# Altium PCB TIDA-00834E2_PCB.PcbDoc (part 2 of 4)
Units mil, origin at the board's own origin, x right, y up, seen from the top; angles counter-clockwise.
Board outline 7480.31 x 4133.86 mil, 4 copper layers (Top Layer, GND, PWR, Bottom Layer), stack 61.912 mil thick; 550 components, 248 nets, 1167 pads, 312 vias.
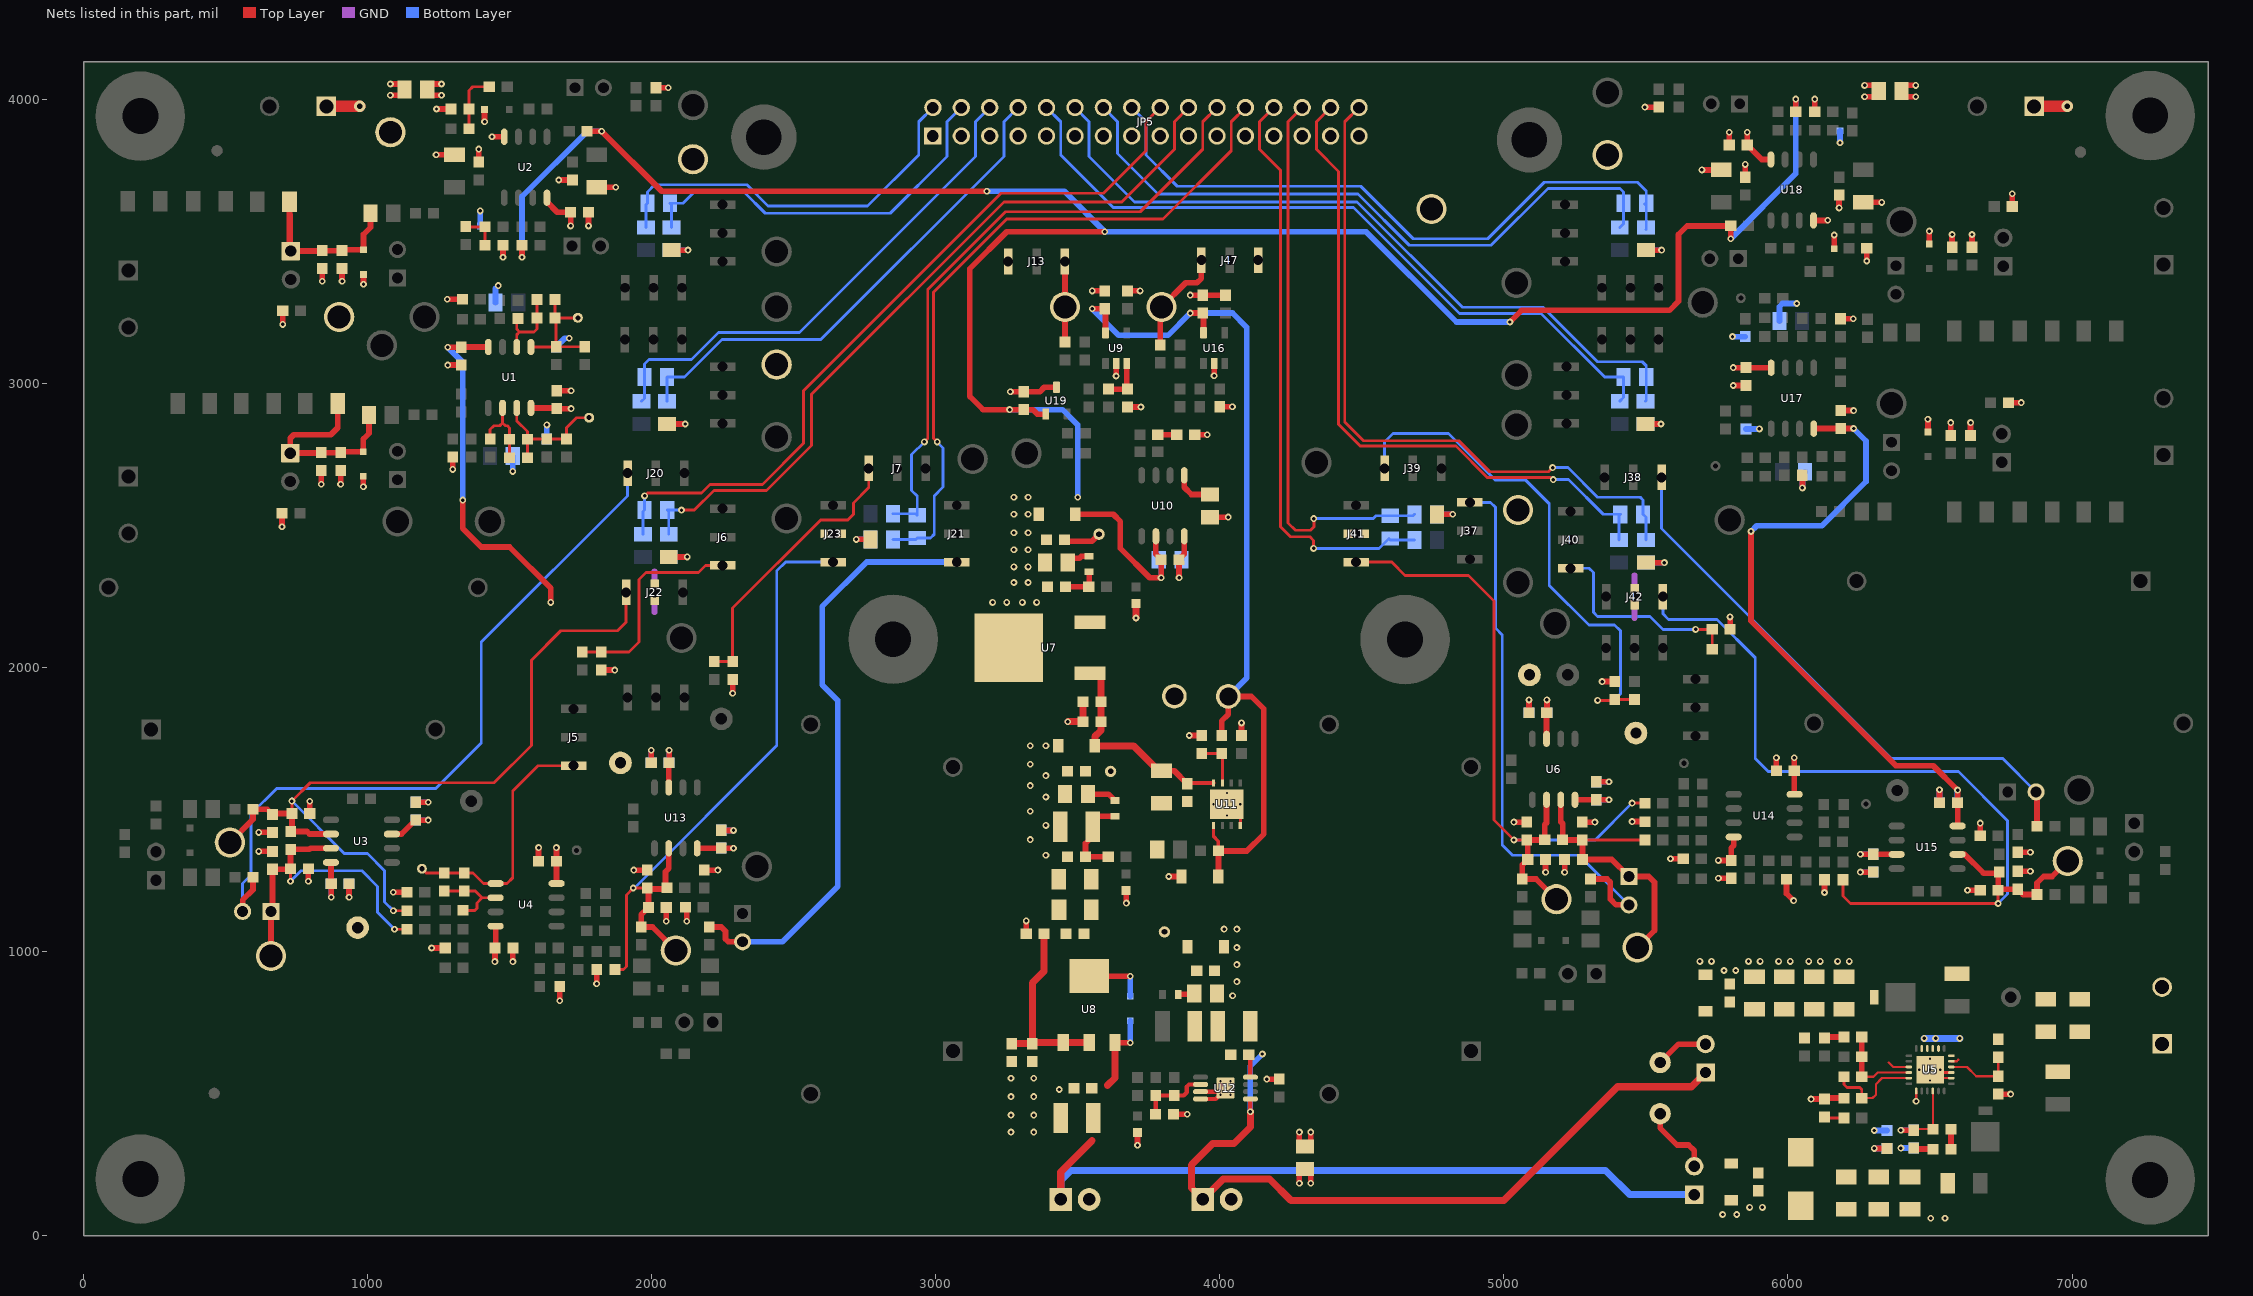
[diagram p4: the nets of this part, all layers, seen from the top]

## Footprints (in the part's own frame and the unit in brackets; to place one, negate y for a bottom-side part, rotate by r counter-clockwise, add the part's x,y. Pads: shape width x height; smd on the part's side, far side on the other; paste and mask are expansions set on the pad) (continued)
TSW-102-07-G-S [mm] "Samtec 100mil, 1x2, 230 mil above insulator"
  rrect6% 1.65x1.65 hole 1.016: 1(-1.27,0)
  round 1.65 hole 1.016: 2(1.27,0)
  silkscreen extent -2.54,-1.27 2.54,1.65, body extent -2.54,-1.27 2.54,1.27, height 8.38
XFMR_CR8350-2500-N [mil] "CURRENT TRANSFORMERS, VERTICAL, 4 PIN, THRU"
  rect 69.06x69.06 / inner round 69.06 / far side rect 69.06x69.06 hole 49.37: 1(-250,500)
  round 69.06 hole 49.37: 2(-250,-500) 3(250,650) 4(250,-650)
  silkscreen extent -317,-738 276,738, body extent -276,-738 276,738, height 1535

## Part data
C1 C2 C4 C5 C19 C20 C82 C84 C88 C90 C99 C100 C101 C102 C104 C105: "CAP, CERM, 100pF, 25V, +/-10%, X7R, 0603"
C3 C6 C9 C66 C103 C106 C110: "CAP, CERM, 0.1uF, 25V, +/-5%, X7R, 0603"
C7 C8 C107 C108: "CAP, CERM, 1000pF, 50V, +/-5%, C0G/NP0, 0603"
C10 C11 C109 C111 C120 C121: "CAP, CERM, 0.01uF, 25V, +/-5%, C0G/NP0, 0603"
C12 C18 C43 C75 C81 C85 C92 C98: library part C1608X5R1C105K, "CAP, CERM, 1 µF, 16 V, +/- 10%, X5R, 0603"
C13 C17 C44 C76 C80 C83 C86 C87 C89 C91 C93 C97: "CAP, CERM, 0.1 µF, 25 V, +/- 10%, X8R, AEC-Q200 Grade 0, 0603"
C14 C16 C47 C52 C77 C79 C94 C96: "CAP, CERM, 1000 pF, 50 V, +/- 10%, X7R, 0603"
C15 C48 C54 C70 C74 C78 C95: library part 06031C103JAT2A, "10000pF 100V Ceramic Capacitor X7R 0603"
C21 C22 C23 C24 C112 C113 C114 C115: "CAP, CERM, 0.01 µF, 50 V, +/- 10%, X7R, 0805"
C25: "CAP, TA, 4.7 µF, 25 V, +/- 10%, 2 ohm, SMD"
C26 C27 C28 C29 C36 C38 C39 C40 C41: "CAP, CERM, 4.7 µF, 25 V, +/- 20%, X7R, 1206"
C30 C33 C35 C42: "CAP, CERM, 0.01 µF, 6.3 V, +/- 10%, X7R, 0603"
C31: library part C0603C224K4RACTU, "CAP, CERM, 0.22 µF, 6.3 V, +/- 10%, X7R, 0603"
C32 C34: "CAP, CERM, 10 pF, 50 V, +/- 5%, C0G/NP0, 0603"
C37: "CAP, CERM, 1 µF, 25 V, +/- 10%, X5R, 0603"
C45 C55 C68: library part C2012X5R1H475K125AB, "CAP, CERM, 4.7uF, 50V, +/-10%, X5R, 0805"
C46 C51 C56 C58 C69 C71 C118 C119: "CAP, CERM, 0.1uF, 50V, +/-10%, X7R, 0603"
C49 C50: library part GRM188R61H105KAALD, "CAP, CERM, 1uF, 50V, +/-10%, X5R, 0603"
C53 C116: "CAP, CERM, 0.1uF, 16V, +/-5%, X7R, 0603"
C57 C60 C67 C72: "CAP, CERM, 10uF, 35V, +/-20%, X7R, 1210"
C59: "CAP, CERM, 0.47uF, 50V, 10%, X5R, 0603"
C61 C62: "CAP, CERM, 1uF, 10V, +/-10%, X7R, 0805"
C63 C117: "CAP, CERM, 0.1uF, 10V, +/-10%, X7R, 0603"
C64: "CAP, CERM, 10uF, 16V, +/-20%, X5R, 0603"
C65: library part GRM31CR71E106KA12L, "CAP, CERM, 10uF, 25V, +/-10%, X7R, 1206"
C73: "CAP, CERM, 2.2uF, 10V, +/-10%, X7R, 0805"
C122: "CAP, CERM, 3.3 µF, 35 V, +/- 10%, X5R, 0603"
D1 D2 D3 D9 D15 D16 D17 D18: library part PESD3V3L1BA, "TVS DIODE 12VWM 37VC SOD323"
D4 D7: "Diode, Schottky, 20 V, 1 A, POWERMITE"
D5 D6 D11 D13: "Diode, Zener, 15V, 1W, SOD-123"
D8: library part MMSZ4685-V, "Diode, Zener, 3.6V, 500mW, SOD-123"
D10 D12 D14: "LED, Green, SMD"
D19 D20 D21 D22: "Diode, Switching, 100 V, 0.2 A, SOD-323"
D23: "Diode, Zener, 5.6 V, 500 mW, SOD-123"
D24: "Diode, Ultrafast, 100 V, 0.25 A, SOD-323"
FB1 FB2 FB3: "Ferrite Bead, 1000 ohm @ 100 MHz, 0.3 A, 0603"
FID1 FID2 FID3 FID4 FID5 FID6: "Fiducial mark.  There is nothing to buy or mount."
H1 H2 H3 H4 H13 H15: "Machine Screw, Round, #4-40 x 1/4, Nylon, Philips panhead"
H5 H6 H7 H8 H14 H16: "Standoff, Hex, 0.5\"L #4-40 Nylon"
H9 H11: "MACHINE SCREW PAN PHILLIPS 4-40"
H10 H12: "Hex Standoff, #4-40, Aluminum, 1/4\""
J1 J2 J10 J31 J34 J48 J49: "TERMINAL BLOCK 5.08MM VERT 2POS, TH"
J3 J4 J17 J18 J19 J26 J27 J29 J32 J33 J35 J36: "Header, Male 2-pin, 100mil spacing,"
J5 J6 J7 J8 J9 J13 J14 J20 J21 J22 J23 J24 J25 J28 J30 J37 J38 J39 J40 J41 J42 J43 J44 J45 J46 J47: "Header, 2.54mm, 3x1, Gold, TH"
J11 J12: "Terminal Block, 4x1, 2.54mm, TH"
J15 J16 JP1 JP2 JP3 JP4 JP6 JP7 JP8 JP9: library part TSW-102-07-G-S, "Header, 100mil, 2x1, Gold, TH"
JP5: library part SSW-116-01-G-D, "Receptacle, 2.54mm, 16x2, Gold, TH"
L1 L2 L5 L6 L7 L8 L9 L10 L11 L12 L13 L14 L15 L16 L17 L18: "Ferrite Bead, 21 ohm @ 100 MHz, 6 A, 0805"
L3 L4: "Inductor, Shielded, Ferrite, 4.7uH, 1.83A, 0.1 ohm, SMD"
LBL1: library part THT-14-423-10, "Thermal Transfer Printable Labels, 0.650\" W x 0.200\" H - 10,000 per roll"
LOGO: library part IEC_HighVoltage, "IEC 61010-1 High Voltage Warning"
Logo1: library part TI_Logo, "Texas Instrument Corporate Signature"
Logo2: library part Pb-Free
Logo3: library part FCC_disclaimer, "FCC_disclaimer"
R1 R3 R138 R140: "RES, 56.2 k, 1%, 0.1 W, 0603"
R2 R4 R5 R7 R11 R16 R139 R141 R142 R144 R148 R153: "RES, 330 k, 1%, 0.25 W, 1206"
R6 R9 R12 R13 R24 R27 R30 R33 R82 R143 R146 R149 R150 R161 R164 R167 R170: library part RNCF0603TKY10K0, "RES, 10.0k ohm, 1%, 0.1W, 0603"
R8 R10 R26 R32 R45 R99 R118 R134 R145 R147 R163 R169 R196 R197: "RES, 100 ohm, 1%, 0.1W, 0603"
R14 R15 R17 R18 R151 R152 R154 R155: "RES, 68.0 k, 1%, 0.1 W, 0603"
R19 R21 R156 R158: "RES, 3.90 k, 1%, 0.1 W, 0603"
R20 R22 R157 R159: "RES, 30.0 k, 1%, 0.1 W, 0603"
R23 R29 R160 R166: "RES, 1.00Meg ohm, 1%, 0.1W, 0603"
R25 R31 R88 R162 R168: "RES, 10.0k ohm, 1%, 0.1W, 0603"
R28 R34 R165 R171: "RES, 1.00k ohm, 1%, 0.25W, 1206"
R35 R41 R89 R95 R106 R112 R122 R128: "RES, 249, 0.1%, 0.1 W, 0603"
R36 R40 R47 R48 R80 R86 R90 R94 R101 R102 R107 R111 R120 R121 R123 R127 R136 R137: "RES, 100 k, 1%, 0.1 W, 0603"
R37 R91 R108 R124: "RES, 169, 1%, 0.1 W, 0603"
R38 R92 R109 R125: "RES, 5.60 k, 0.1%, 0.1 W, 0603"
R39 R93 R110 R126: "RES, 15.0, 1%, 0.1 W, 0603"
R42 R57 R59 R62 R63 R65 R96 R104 R105 R113 R114 R116 R129 R130 R132 R198 R199 R200 R201 R202 R203 R204 R205: "RES, 0, 5%, 0.1 W, 0603"
R43 R97 R115 R131: "RES, 82.0 k, 0.1%, 0.1 W, 0603"
R44 R46 R98 R100 R117 R119 R133 R135: "RES, 8.20 k, 1%, 0.1 W, 0603"
R49 R50 R51 R52 R53 R54 R55 R56 R173 R174 R175 R176 R177 R178 R179 R180: "RES, 1.00 k, 1%, 0.125 W, 0805"
R58: "RES, 0 ohm, 5%, 0.25W, 1206"
R60: "RES, 576 k, 1%, 0.1 W, 0603"
R61 R66 R67: "RES, 49.9 k, 0.1%, 0.1 W, 0603"
R64: library part RC0603FR-07620KL, "RES SMD 620K OHM 1% 1/10W 0603"
R68: library part RT0603DRE071RL, "RES SMD 1 OHM 5% 1/10W 0603"
R69: "RES, 1.0 k, 5%, 0.1 W, 0603"
R70 R103 R172: library part CRCW0805330KJNEA, "RES, 0 ohm, 5%, 0.125W, 0805"
R71: "RES, 300 ohm, 5%, 0.1W, 0603"
R72 R73 R77 R78 R81 R83 R189 R190 R191 R192 R193 R194 R195 R206 R207: "RES, 0 ohm, 5%, 0.1W, 0603"
R74 R84: "RES, 3.9k ohm, 5%, 0.1W, 0603"
R75 R76: "RES, 2.00 k, 1%, 0.25 W, 1206"
R79: "RES, 8.45 k, 1%, 0.1 W, 0603"
R85: "RES, 1.07 M, 1%, 0.1 W, 0603"
R87: "RES, 31.6k ohm, 1%, 0.1W, 0603"
R181 R182 R183 R184 R185 R186 R187 R188: "RES, 100 k, 1%, 0.125 W, 0805"
T1 T2 T3 T4: "CURRENT TRANSFORMER, 20-1 KHz, 57 OHM, VERTICAL, THRU-4P"
TP1 TP2 TP5 TP6 TP11 TP12 TP13 TP14 TP18 TP21 TP25 TP31 TP32 TP33 TP34 TP35 TP36 TP37 TP38 TP42 TP43 TP46 TP47 TP48 TP49 TP50 TP51 TP52 TP53 TP54 TP55 TP56 TP57 TP58 TP59 TP60 TP61 TP62 TP63 TP64: library part 1573-2, "Terminal, Turret, TH, Double"
TP3 TP4 TP10 TP17 TP28 TP30 TP41 TP44 TP45: "Test Point, O.040 Hole"
TP7 TP8 TP27 TP39: "Test Point, Miniature, White, TH"
TP9 TP26 TP29 TP40: "Test Point, Miniature, Black, TH"
TP15 TP16: "Test Point,  Black, Thru Hole Color Keyed"
TP19 TP20 TP22: library part TP-040_RND, "Test Point 40mil pad 20mil drill"
TP23: library part 5010, "Test Point, Multipurpose, Red, TH"
TP24: library part 5126, "Test Point, Multipurpose, Green, TH"
U1 U4 U14 U17: "0.03 uV/degC, 6 uV Vos, Low Noise, Rail-to-Rail Output, Zero-Drift Operational Amplifier, 4 to 36 V, -40 to 105 degC, 8-pin SOIC (D0008A), Green (RoHS & no Sb/Br)"
U2 U18: library part LM2903D, "Dual Comparator, D0008A"
U3 U6 U13 U15: library part INA188D, "INA188 Precision, Zero-Drift, Rail-to-Rail Out, High Voltage Instrumentation Amplifier, D0008A"
U5: "Postive and Negative Output DC-DC Converter, 2.7 to 5.5 V, -40 to 85 degC, 24-pin QFN (RGE24), Green (RoHS & no Sb/Br)"
U7: "IC, 300-mA 40-V LOW-DROPOUT REGULATOR WITH 25-uA QUIESCENT CURRENT"
U8: "IC,  vvV, 800mA LDO Voltage Regulators"
U9 U16: "20 MHz, Low Noise, RRIO, CMOS Operational Amplifier with Shutdown, 1.8 to 5.5 V, -40 to 125 degC, 5-pin SOT23 (DBV0005A), Green (RoHS & no Sb/Br)"
U10: "Low-Noise, Very Low Drift, Precision VOLTAGE REFERENCE, 2.5V, D008A"
U11: "Series of Adjustable Micropower Voltage Regulators, 8-pin LLP"
U12: "Single Output High PSRR LDO, 200 mA, Adjustable -1.18 to -33 V Output, -3 to -36 V Input, with Ultra-Low Noise, 8-pin MSOP (DGN), -40 to 125 degC, Green (RoHS & no Sb/Br)"
U19: "2.5 V, 50 ppm / degC, 50 uA Series (Bandgap) Voltage Reference, -40 to 125 degC, 3-pin SOT-23 (DBZ), Green (RoHS & no Sb/Br)"
ZZ1: library part AssemblyNoteLabel
ZZ2 ZZ3 ZZ4: library part AssemblyNote

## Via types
v1: diameter 24, hole 12, Top Layer to Bottom Layer, tented both sides, 295 vias
v2: diameter 19.68, hole 7.87, Top Layer to Bottom Layer, tented both sides, 15 vias
v3: diameter 40, hole 20, Top Layer to Bottom Layer, 2 vias

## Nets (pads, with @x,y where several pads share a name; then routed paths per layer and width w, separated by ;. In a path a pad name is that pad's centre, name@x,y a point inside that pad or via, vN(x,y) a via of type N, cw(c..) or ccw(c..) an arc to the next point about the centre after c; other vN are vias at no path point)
+2.5V: J13.1 R77.1 TP21.1 | length 283.5
  Top Layer w20: R77.1@3455,3146.5 TP21.1@3455,3270 J13.1@3455,3430
+2.5VB: J47.1 R191.1 TP55.1 | length 382
  Top Layer w20: R191.1@3790,3136.5 3790,3265 TP55.1@3795,3270 3880,3355 3920,3355 3935,3370 J47.1@3935,3435
+3.3V: C45.1 C46.1 C62.1 C118.1 C119.1 D8.1 FB1.2 R25.2 R31.2 R162.2 R168.2 TP19.1 U10.2 U19.1 | length 8565.2
  Top Layer w20: v1(1543.5,3445) R31.2@1543.5,3486.85 ; R25.2@1775.55,3888.51 v1(1823.73,3888.51) 2035.24,3677 v1(3180,3677) ; U19.1@3387.6,2892.76 3357.24,2892.76 3341.5,2908.5 C118.1@3310,2908.5 v1(3260,2908.5) 3166.5,2908.5 3120,2955 3120,3405 3250,3535 v1(3595,3535) ; C46.1@3453.35,2450 3458.35,2445 3550,2445 TP19.1@3575,2470 ; C45.1@3465,2370 3480,2385 3505,2385 3512.56,2392.56 FB1.2@3540,2392.56 ; D8.1@3491.32,2540 3625,2540 3650,2515 3650,2420 3753.5,2316.5 v1(3793.5,2316.5) C119.1@3793.5,2380 3793.5,2381.5 3775,2400 U10.2@3775,2462.72 ; v1(5021,3217) 5062,3258 5583,3258 5615,3290 5615,3525 5645.19,3555.19 R162.2@5798.51,3555.19 v1(5798.51,3510.19) ; R168.2@6027.62,3956.68 v1(6027.62,4001.68)
  Bottom Layer w20: v1(1543.5,3445) 1543.5,3658.5 1773.51,3888.51 v1(1823.73,3888.51) ; v1(3180,3677) 3453,3677 v1(3595,3535) 4515,3535 4833,3217 v1(5021,3217) ; v1(3260,2908.5) 3446.5,2908.5 3500,2855 v1(3500,2600) ; C62.1@3785,2380 3793.5,2371.5 v1(3793.5,2316.5) ; v1(5798.51,3510.19) 6027.62,3739.3 v1(6027.62,4001.68)
+5V: C53.2 C116.2 D23.1 R83.2 R87.2 TP23.1 U9.5 U11.1 U16.5 | length 3309.3
  Top Layer w12: U11.1@3977.76,1444.57 3977.76,1407.24 3995.2,1389.8 R83.2@3995.2,1355
  Top Layer w20: v1(3550.8,3263.5) C53.2@3595,3263.5 3597.6,3260.91 U9.5@3597.6,3178.82 ; v1(3895.8,3248.5) C116.2@3940,3248.5 3942.6,3245.91 U16.5@3942.6,3179.13 ; D23.1@3994.47,1265 3995.2,1265.73 R83.2@3995.2,1355 4095,1355 4155,1415 4155,1855 4111.13,1898.87 TP23.1@4030,1898.87 4030,1836.39 4006.3,1812.69 R87.2@4006.3,1761.5
  Bottom Layer w20: v1(3550.8,3263.5) 3644.31,3170 3817.3,3170 v1(3895.8,3248.5) 4044.7,3248.5 4095,3198.2 4095,1963.87 TP23.1@4030,1898.87
+5V_IN: C26.1 C38.1 J10.1 L3.1 R68.1 U5.5 U5.6 U5.8 U5.9 U5.10 U5.11 | length 152.1
  Top Layer w8: U5.5@6575.28,614.33 6594.33,614.33 6600,620
  Bottom Layer w25: v1(6480,695) v1(6520,695) v1(6605,695)
+12V: C3.2 C9.2 C17.1 C18.1 C50.1 C51.1 C55.1 C56.1 C65.1 C66.1 C80.1 C81.1 C83.1 C85.1 C86.1 C89.1 C97.1 C98.1 C103.2 C110.2 D11.1 FB2.2 R24.2 R30.2 R82.2 R161.2 R167.2 TP20.1 U1.8 U2.8 U3.7 U4.8 U6.7 U7.1 U11.8 U13.7 U14.8 U15.7 U17.8 U18.8 | length 2670.4
  Top Layer w15: C66.1@3887.68,1594.17 U11.8@3977.76,1594.17
  Top Layer w20: U3.7@1085.47,1414.33 1119.33,1414.33 1168.49,1463.49 C17.1@1170,1463.49 v1(1213.68,1463.49) ; R30.2@1391.12,3780 v1(1391.12,3825.73) ; U1.8@1575,2914.57 1663.56,2914.57 C3.2@1666.12,2912.01 v1(1716.14,2912.01) ; U2.8@1631.12,3654.57 1631.12,3640.07 1667.68,3603.51 C9.2@1714.62,3603.51 v1(1714.62,3555.33) ; v1(1664.76,1366.58) C86.1@1664.76,1318.4 1664.76,1240.82 U4.8@1665.24,1240.34 ; v1(1672.94,3717.01) R24.2@1721.12,3717.01 ; U13.7@2060,1578.73 2060,1664.41 C81.1@2061.5,1665.9 v1(2061.5,1709.58) ; C55.1@3535.53,1555 3608.09,1555 FB2.2@3630.53,1532.56 ; C65.1@3795,1637.09 3839.41,1637.09 C66.1@3885,1591.5 ; R82.2@4076.3,1761.5 v1(4076.3,1805.69) ; U6.7@5150.31,1749.69 5150.31,1840.92 C83.1@5151.18,1841.78 ; C83.1@5151.5,1841.72 v1(5151.5,1886.72) ; v1(5807.26,3056.5) C103.2@5852.26,3056.5 5852.77,3055.98 U17.8@5940.96,3055.98 ; R161.2@5850,3726.68 v1(5850,3771.68) ; v1(5856.5,3885.19) C110.2@5856.5,3840.19 5907.56,3789.13 U18.8@5940,3789.13 ; v1(6022.28,1682.8) C89.1@6022.28,1637.8 6022.28,1555.66 U14.8@6023.65,1554.29 ; v1(6180,3618.69) R167.2@6180,3663.69 ; v1(6255,1343.31) C97.1@6300,1343.31 6300.52,1342.8 U15.7@6382.72,1342.8
  Top Layer w25: U7.1@3543.11,1979.84 3581.5,1979.84 C50.1@3581.5,1880 C51.1@3581.5,1810 3581.5,1779 3560,1757.5 D11.1@3560,1725 3696,1725 3783.91,1637.09 C65.1@3795,1637.09
  Bottom Layer w20: C18.1@1170,1463.49 v1(1213.68,1463.49) ; C80.1@2061.5,1665.9 v1(2061.5,1709.58) ; C85.1@5151.5,1841.72 v1(5151.5,1886.72) ; v1(6255,1343.31) C98.1@6300.07,1343.31
+14V: C57.1 C58.1 D24.1 J11.1 J15.1 U8.3 | length 2893.9
  Top Layer w15: C58.1@3547.2,522.2 C58.1@3549.41,520
  Top Layer w20: U8.3@3631,680 v1(3685,680)
  Top Layer w25: J11.1@3440,127.95 3440,225 3550,335 ; 3605,530 3631,556 U8.3@3631,680
  Bottom Layer w20: v1(3685,680) D24.1@3685,756.69
  Bottom Layer w25: J11.1@3440,127.95 3440,195 3475,230 5358,230 5443,145 J15.1@5670,145
-12V: C6.2 C12.1 C13.1 C43.1 C44.1 C68.2 C71.1 C75.1 C76.1 C87.1 C91.1 C92.1 C93.1 C106.2 D13.2 FB3.2 TP22.1 U1.4 U3.4 U4.4 U6.4 U13.4 U14.4 U15.4 U17.4 | length 4315.6
  Top Layer w20: U3.4@870.91,1314.33 870.91,1240.11 C13.1@871.69,1239.33 v1(871.69,1191.69) ; v1(1281.82,3128.35) C6.2@1330,3128.35 1330.79,3129.14 U1.4@1425,3129.14 ; v1(1335,2590) 1335,2490 1400,2425 1500,2425 1645,2280 v1(1645,2230) ; v1(1448.26,965.22) C87.1@1448.26,1013.4 1450.67,1015.81 U4.4@1450.67,1090.34 ; U13.4@2160,1364.17 C76.1@2244.21,1364.17 ; C76.1@2245,1364.95 C76.1@2244.21,1364.17 ; v1(2287.9,1364.17) C76.1@2244.21,1364.17 ; FB3.2@3853.34,850.13 3907.69,850.13 C68.2@3910.31,852.75 ; U6.4@5250.31,1535.12 5324.83,1535.12 C44.1@5325.07,1535.35 v1(5370.07,1535.35) ; v1(5755,1321.5) C91.1@5800,1321.5 5800,1365 5809.09,1374.09 U14.4@5809.09,1404.29 ; v1(5870,2480) 5870,2165 6380,1655 6511.57,1655 v1(6597.28,1569.28) C93.1@6597.28,1524.28 ; U17.4@6090.96,2841.42 6091.74,2842.2 C106.2@6185.96,2842.2 v1(6230.96,2842.2) ; C93.1@6596.5,1525.07 C93.1@6597.28,1524.28 ; U15.4@6597.28,1442.8 C93.1@6597.28,1524.28
  Bottom Layer w20: v1(871.69,1191.69) C12.1@871.69,1239.33 ; v1(1281.82,3128.35) 1335,3075.17 v1(1335,2590) ; C43.1@5325,1535.35 v1(5370.07,1535.35) ; v1(5870,2480) 5890,2500 6120,2500 6275,2655 6275,2798.16 v1(6230.96,2842.2) ; C92.1@6596.5,1525 6596.5,1568.49 v1(6597.28,1569.28)
-14V: C67.2 C69.1 J12.1 J16.1 U12.5 U12.8 | length 2820.1
  Top Layer w15: C69.1@4101.8,637.75 4107.6,631.96 U12.8@4107.6,558.65 ; v1(4107.6,436.71) U12.5@4107.6,481.88
  Top Layer w25: v1(4107.6,436.71) 4107.6,382.6 4050,325 3975,325 3900,250 3900,167.95 J12.1@3940,127.95 4012.05,200 4175,200 4250,125 5000,125 5400,525 5660,525 J16.1@5710,575
  Bottom Layer w20: v1(4107.6,436.71) 4107.6,597.6 v1(4150,640)
ACI_OUT1: C21.1 JP5.18 R49.2 | length 2686.3
  Top Layer w10: v1(1975,2605) 1985,2615 2175,2615 2205,2645 2390,2645 2535,2790 2535,2975 3230,3670 3590,3670 3740,3820 3740,3921.85 JP5.18@3790,3971.85
  Bottom Layer w10: R49.2@1970,2470 1970,2550 C21.1@1975,2555 v1(1975,2605)
ACI_OUT1_GND: C21.2 JP5.20 R51.2 | length 2671.1
  Top Layer w10: v1(2105,2555) 2150,2555 2219,2624 2404,2624 2562.5,2782.5 2562.5,2962.5 3240,3640 3655,3640 3840,3825 3840,3921.85 JP5.20@3890,3971.85
  Bottom Layer w10: R51.2@2060,2470 2060,2550 C21.2@2055,2555 v1(2105,2555)
ACI_OUT2: C22.1 JP5.22 R50.2 | length 2253.9
  Top Layer w10: v1(2960,2795) 2972,2807 2972,3332 3245,3605 3720,3605 3940,3825 3940,3921.85 JP5.22@3990,3971.85
  Bottom Layer w10: R50.2@2850,2541.85 2930,2541.85 C22.1@2935,2536.85 2935,2604 2915,2624 2915,2750 v1(2960,2795)
ACI_OUT2_GND: C22.2 JP5.24 R52.2 | length 2458.3
  Top Layer w10: v1(3005,2795) 2992,2808 2992,3322 3250,3580 3800,3580 4040,3820 4040,3921.85 JP5.24@4090,3971.85
  Bottom Layer w10: R52.2@2850,2451.85 2930,2451.85 C22.2@2935,2456.85 2981.85,2456.85 2995,2470 2995,2605 3026,2636 3026,2774 v1(3005,2795)
ACI_OUT3: C112.1 JP5.26 R173.2 | length 2062.8
  Top Layer w10: JP5.26@4190,3971.85 4140,3921.85 4140,3825 4214,3751 4214,2496 4249,2461 4317.24,2461 4330,2448.24 v1(4330,2420)
  Bottom Layer w10: v1(4330,2420) 4560,2420 4595,2455 4600,2450 R173.2@4685,2450
ACI_OUT3_GND: C112.2 JP5.28 R175.2 | length 1978.5
  Top Layer w10: JP5.28@4290,3971.85 4240,3921.85 4240,2510 4266,2484 4319,2484 4331,2496 v1(4331,2525)
  Bottom Layer w10: v1(4331,2525) 4540,2525 4550,2535 C112.2@4600,2535 4680,2535 R175.2@4685,2540
ACI_OUT4: C113.1 JP5.30 R174.2 | length 2383.2
  Top Layer w10: JP5.30@4390,3971.85 4340,3921.85 4340,3825 4418,3747 4418,2857 4494.14,2780.86 4830.86,2780.86 4941.72,2670 5166,2670 v1(5174,2662)
  Bottom Layer w10: v1(5174,2662) 5228,2662 5349.99,2540.01 C113.1@5410,2540.01 5405,2535.01 R174.2@5405,2450.01
ACI_OUT4_GND: C113.2 JP5.32 R176.2 | length 2447.6
  Top Layer w10: JP5.32@4490,3971.85 4440,3921.85 4440,2865 4506.27,2798.73 4841.27,2798.73 4950,2690 5157,2690 v1(5171.5,2704.5)
  Bottom Layer w10: v1(5171.5,2704.5) 5225.5,2704.5 5330,2600 5480,2600 5490,2590 C113.2@5490,2540.01 5500,2530.01 R176.2@5500,2450.01
ACV_OUT1: C23.1 JP5.2 R53.2 | length 1385.6
  Bottom Layer w10: R53.2@1980,3550 1980,3630 C23.1@1985,3635 1985,3675 2010,3700 2335,3700 2410,3625 2760,3625 2940,3805 2940,3921.85 JP5.2@2990,3971.85
ACV_OUT1_GND: C23.2 JP5.4 R55.2 | length 1385.1
  Bottom Layer w10: R55.2@2070,3550 2070,3630 C23.2@2065,3635 2110,3635 2150,3675 2325,3675 2400,3600 2840,3600 3040,3800 3040,3921.85 JP5.4@3090,3971.85
ACV_OUT2: C24.1 JP5.6 R54.2 | length 1796.3
  Bottom Layer w10: R54.2@1964.43,2938.05 1974.43,2948.05 C24.1@1974.43,3023.05 1974.43,3069.43 1990,3085 2140,3085 2235,3180 2520,3180 3140,3800 3140,3921.85 JP5.6@3190,3971.85
ACV_OUT2_GND: C24.2 JP5.8 R56.2 | length 1784.9
  Bottom Layer w10: R56.2@2054.43,2938.05 C24.2@2054.43,3023.05 2116.05,3023.05 2248,3155 2595,3155 3240,3800 3240,3921.85 JP5.8@3290,3971.85
ACV_OUT3: C114.1 JP5.10 R177.2 | length 2582.9
  Bottom Layer w10: JP5.10@3390,3971.85 3440,3921.85 3440,3805 3625,3620 4471,3620 4844,3247 5131,3247 5354.95,3023.05 C114.1@5421.06,3023.05 5421.06,2951.11 R177.2@5408,2938.05
ACV_OUT3_GND: C114.2 JP5.12 R179.2 | length 2585.1
  Bottom Layer w10: JP5.12@3490,3971.85 3540,3921.85 3540,3800 3700,3640 4483,3640 4854,3269 5138,3269 5330,3077 5487.11,3077 5501.06,3063.05 C114.2@5501.06,3023.05 5501.06,2941.11 R179.2@5498,2938.05
ACV_OUT4: C115.1 JP5.14 R178.2 | length 2315.6
  Bottom Layer w10: JP5.14@3590,3971.85 3640,3921.85 3640,3810 3782.5,3667.5 4486.5,3667.5 4667,3487 4955,3487 5155,3687 5409.06,3687 5421.06,3675 C115.1@5421.06,3635 5421.06,3563.06 R178.2@5408,3550
ACV_OUT4_GND: C115.2 JP5.16 R180.2 | length 2304
  Bottom Layer w10: JP5.16@3690,3971.85 3740,3921.85 3740,3805 3850,3695 4496,3695 4681,3510 4943,3510 5142,3709 5470.06,3709 5501.06,3678 C115.2@5501.06,3635 5501.06,3543.69 R180.2@5500.38,3543 ; C115.2@5495.38,3633 C115.2@5497.22,3631.16
AGND: C3.1 C4.2 C5.2 C6.1 C7.1 C8.1 C12.2 C13.2 C14.2 C16.1 C17.2 C18.2 C20.2 C43.2 C44.2 C45.2 C46.2 C47.2 C49.2 C50.2 C51.2 C52.1 C53.1 C55.2 C56.2 C57.2 C58.2 C59.2 C60.2 C61.2 C62.2 C63.1 C64.2 C65.2 C66.2 C67.1 C68.1 C69.2 C71.2 C72.1 C73.2 C74.1 C75.2 C76.2 C77.2 C79.1 C80.2 C81.2 C83.2 C84.2 C85.2 C86.2 C87.2 C89.2 C90.2 C91.2 C92.2 C93.2 C94.2 C96.1 C97.2 C98.2 C100.2 C103.1 C104.2 C105.2 C106.1 C107.1 C108.1 C116.1 C117.1 C118.2 C119.2 C122.2 D1.2 D2.2 D8.2 D10.2 D11.2 D12.2 D13.1 D14.1 D17.2 D18.2 D23.2 J13.3 J22.2 J23.2 J41.2 J42.2 J47.3 J48.1 J49.1 JP5.1 JP5.3 JP5.5 JP5.7 JP5.9 JP5.11 JP5.13 JP5.15 JP5.17 JP5.19 JP5.21 JP5.23 JP5.25 JP5.27 JP5.29 JP5.31 L11.1 L12.1 L15.1 L16.1 R15.1 R18.1 R19.1 R20.1 R21.1 R22.1 R36.1 R40.2 R42.1 R48.1 R51.1 R52.1 R55.1 R56.1 R70.1 R79.1 R80.1 R86.1 R88.1 R90.1 R94.2 R96.2 R102.1 R103.1 R107.1 R111.2 R116.1 R121.1 R123.1 R127.2 R132.2 R137.1 R152.1 R155.1 R156.1 R157.1 R158.1 R159.1 R172.1 R175.1 R176.1 R179.1 R180.1 R181.1 R182.1 R183.1 R184.1 R185.1 R186.1 R187.1 R188.1 R206.2 R207.2 TP9.1 TP24.1 TP26.1 TP29.1 TP32.1 TP33.1 TP34.1 TP36.1 TP37.1 TP40.1 TP53.1 TP54.1 U7.2 U9.2 U10.4 U11.4 U11.9 U12.3 U12.4 U12.9 U16.2 U19.3 | length 7302.8
  Top Layer w10: U11.4@4072.24,1444.57 U11.9@4072.24,1472.13
  Top Layer w15: C84.2@2285,1958.5 C84.2@2285,1965 ; U12.4@3932.4,481.88 3985.66,481.88 4007.2,503.42 U12.9@4007.2,507.47 ; U12.3@3932.4,507.47 U12.9@4007.2,507.47 ; v2(4020,520.26) U12.9@4007.2,507.47
  Top Layer w20: v1(616.81,1353.34) C14.2@665,1353.34 ; v1(616.81,1420.35) C16.1@665,1420.35 ; v1(698.5,2496.03) R21.1@698.5,2544.21 ; v1(701.02,3208.67) R19.1@701.02,3256.85 ; v1(791.49,1248.17) R36.1@791.49,1291.85 ; R40.2@796.49,1486.85 v1(796.49,1530.17) ; v1(837,2645.87) R22.1@837,2694.06 ; v1(840,3360.62) R20.1@840,3408.8 ; v1(905,2645.87) C8.1@905,2694.06 ; v1(910,3360.62) C7.1@910,3408.8 ; v1(934.68,1191.69) C13.2@934.68,1239.33 ; v1(985,2636.85) D2.2@985,2673.55 ; v1(985.48,3350.21) D1.2@985.48,3384.27 ; v1(1080,4015) 1130,4015 R172.1@1130,4035 1130,4050 1125,4055 v1(1080,4055) ; v1(1090,1209.4) R42.1@1138.18,1209.4 ; C17.2@1170,1526.48 v1(1213.68,1526.48) ; v1(1225.08,1013.4) R48.1@1273.26,1013.4 ; v1(1280.55,3296.85) R15.1@1330.57,3296.85 ; v1(1281.82,3065.36) C6.1@1330,3065.36 ; v1(1300,2698) R18.1@1300,2741.7 ; v1(1511.25,965.22) C87.2@1511.25,1013.4 ; C86.2@1601.76,1318.4 v1(1601.76,1366.58) ; C3.1@1666.12,2975 v1(1716.14,2975) ; v1(1676.08,827.71) R102.1@1676.08,877.73 ; v1(1806.08,887.65) R96.2@1806.08,937.67 ; C20.2@1822.09,1991.76 v1(1870.27,1991.76) ; v1(1936.82,1287.4) R94.2@1985,1287.4 ; C81.2@1998.5,1665.9 v1(1998.5,1709.58) ; v1(2051.5,1107.72) C79.1@2051.5,1155.9 ; R185.1@2054.43,2858.05 v1(2118.05,2858.05) ; R181.1@2055,2400 R181.1@2060,2400 ; R181.1@2060,2390 v1(2125,2390) ; R188.1@2070,3470 v1(2128,3470) ; v1(2123.51,1107.72) C77.2@2123.51,1155.9 ; R90.1@2185,1287.4 v1(2233.18,1287.4) ; C76.2@2244.21,1427.16 v1(2287.9,1427.16) ; v1(2285,1909.9) C84.2@2285,1958.5 ; v1(2720,2451.85) R182.1@2770,2451.85 ; v1(3262.76,2971.5) C118.2@3310,2971.5 3366.5,2971.5 3382.24,2987.24 U19.3@3425,2987.24 ; C122.2@3318.5,1064 v1(3318.5,1108.53) ; v1(3550.8,3326.5) C53.1@3595,3326.5 ; v1(3635,3027) U9.2@3635,3070.55 ; v1@3670.53,1170.94 D12.2@3670.53,1215.47 ; C63.1@3675,2917.76 v1(3722.24,2917.76) ; R206.2@3675,3326.5 v1(3719.2,3326.5) ; v1(3710.24,318.62) D14.1@3710.24,363.03 ; v1(3820,1265) D23.2@3865.53,1265 ; R86.1@3836.8,427.75 v1(3885.31,427.75) ; v1(3856.5,2316.5) C119.2@3856.5,2380 3856.5,2381.5 3875,2400 U10.4@3875,2462.72 ; v1(3892.1,1761.5) R88.1@3936.3,1761.5 ; v1(3895.8,3311.5) C116.1@3940,3311.5 R207.2@4020,3311.5 ; C64.2@3911.5,2820 v1(3955.69,2820) ; C61.2@3965,2530 v1(4030,2530) ; v1(3980,3028) U16.2@3980,3070.87 ; C117.1@4000,2918.5 v1(4044.2,2918.5) ; v1(4165.54,551.76) C74.1@4209.04,551.76 ; v1(4280,365) 4280,315 R70.1@4300,315 4315,315 4320,320 v1(4320,365) ; R183.1@4765,2540 v1(4820,2540) ; v1(5035.32,1456.5) R111.2@5080.32,1456.5 ; C83.2@5088.5,1841.72 v1(5088.5,1886.72) ; v1(5146.81,1280) C52.1@5146.81,1325 ; v1(5213.82,1280) C47.2@5213.82,1325 ; R107.1@5275.32,1456.5 v1(5320.32,1456.5) ; C44.2@5325.07,1598.35 v1(5370.07,1598.35) ; v1@5345.47,1951.5 C90.2@5390,1951.5 ; v1(5451.59,1458.34) R116.1@5496.59,1458.34 ; R186.1@5498,2858.05 v1(5553,2858.05) ; R184.1@5500,2370 v1(5565,2370) ; R187.1@5500.38,3470 v1(5555.38,3470) ; v1(5586.67,1327.34) R121.1@5631.67,1327.34 ; v1(5755,1258.5) C91.2@5800,1258.5 ; C100.2@5796.5,2135 v1@5796.5,2179.53 ; v1(5807.26,2993.5) C103.1@5852.26,2993.5 ; C89.2@5959.29,1637.8 v1(5959.29,1682.8) ; R137.1@5995.2,1255 5995.2,1204.8 v1(6020,1180) ; v1(6050.96,2632.83) R152.1@6050.96,2677.83 ; v1(6128.7,1208.5) R132.2@6128.7,1253.5 ; R155.1@6185,3228.35 v1(6230,3228.35) ; C106.1@6185.96,2905.19 v1(6230.96,2905.19) ; v1(6255.07,1280.32) C97.2@6300,1280.32 C97.2@6300.07,1280.32 ; v1(6450,4010) 6405,4010 6400,4015 R103.1@6400,4030 6400,4050 v1(6450,4050) ; D17.2@6492.83,2829.8 v1(6492.83,2874.8) ; D18.2@6497.83,3491.93 v1(6497.83,3536.93) ; C93.2@6533.51,1525.07 v1(6533.51,1570.07) ; C107.1@6572.83,2817.99 v1(6572.83,2862.99) ; C108.1@6577.83,3480.12 v1(6577.83,3525.12) ; v1(6632.01,1216.81) R127.2@6677.01,1216.81 ; R157.1@6642.83,2817.99 v1(6642.83,2862.99) ; R159.1@6647.83,3480.12 v1(6647.83,3525.12) ; R123.1@6677.01,1407.8 v1(6677.01,1452.8) ; R156.1@6776.5,2933.15 v1(6821.5,2933.15) ; R158.1@6789.33,3623.62 v1(6789.33,3668.62) ; C96.1@6808.51,1283.31 v1(6853.51,1283.31) ; C94.2@6808.5,1350.32 v1(6853.5,1350.32)
  Top Layer w25: v1(3465,1810) C51.2@3518.5,1810 C50.2@3518.5,1880 ; v1(3705,2175) D10.2@3705,2225.47
  Top Layer w40: J48.1@854.72,3976.38 v3(971.97,3976.38) ; J49.1@6866.38,3976.38 v3(6983.62,3976.38)
  GND w20: 2010,2195 J22.2@2010,2265 2010,2340 ; 5460,2175 J42.2@5460,2250 5460,2325
  Bottom Layer w20: v1(934.68,1191.69) C12.2@934.68,1239.33 ; C18.2@1170,1526.48 v1(1213.68,1526.48) ; L11.1@1450,3285 1450,3335 v1(1460,3345) ; v1(1511.14,2691.14) L12.1@1511.14,2745 ; C5.2@1631.12,2804.61 v1(1631.12,2854.63) ; C4.2@1663.7,3130 1693.69,3160 v1(1710,3160) ; C80.2@1998.5,1665.9 v1(1998.5,1709.58) ; R56.1@2054.43,2858.05 v1(2118.05,2858.05) ; R51.1@2060,2390 v1(2125,2390) ; R55.1@2070,3470 v1(2128,3470) ; C75.2@2244.21,1427.16 v1(2287.9,1427.16) ; v1(2720,2451.85) R52.1@2770,2451.85 ; v1(3856.5,2316.5) 3856.5,2371.5 C62.2@3865,2380 ; R175.1@4765,2540 v1(4820,2540) ; C85.2@5088.5,1841.72 v1(5088.5,1886.72) ; C43.2@5325,1598.35 v1(5370.07,1598.35) ; R179.1@5498,2858.05 v1(5553,2858.05) ; R176.1@5500,2370.01 v1(5565,2370) ; R180.1@5500.38,3470 v1(5555.38,3470) ; v1(5804.84,3165.55) C105.2@5849.84,3165.55 ; C104.2@5852.26,2840.55 v1(5899.45,2840.55) ; L16.1@5970,3220 5970,3271 5981,3282 v1(6031,3282) ; v1(6050.96,2632.83) 6050.96,2680.96 L15.1@6060,2690 ; v1(6255.07,1280.32) C98.2@6300.07,1280.32 ; C92.2@6533.5,1525 v1(6533.51,1570.07)
  other v1: 3265,365 3345,365 3265,425 3345,425 3265,490 3345,490 3435,515 3265,555 3345,555 4045,845 4060,895 4060,955 4060,1015 4015,1080 4060,1080 3671,1171.42 3387.62,1340 3332.62,1395 3387.62,1445 3332.62,1495 3387.62,1545 3332.62,1585 3387.62,1620 3332.62,1660 3332.62,1725 3387.62,1725 5345.94,1951.02 5796.02,2179.06 3200,2230 3250,2230 3305,2230 3355,2230 3275,2300 3325,2300 3275,2355 3325,2355 3275,2415 3325,2415 3275,2475 3325,2475 3275,2540 3325,2540 3275,2600 3325,2600
  other v2: 4002.28,496.64 4037.72,496.64 4002.28,543.88 4037.72,543.88 4025,1480 3977.76,1519.37 4025,1519.37 4072.24,1519.37 4025,1558.74
CT1_IN_+: J19.2 J20.3 R35.2 | length 2567.9
  Top Layer w20: J19.2@560,1141.85 560,1181.85 596.5,1218.35 R35.2@596.5,1262.17
  Bottom Layer w10: J19.2@560,1141.85 560,1240 590,1270 590,1485 680,1575 1240,1575 1400,1735 1400,2090 1915,2605 J20.3@1915,2685
CT1_IN_-: C15.2 C16.2 J22.3 R40.1 R41.2 R62.2 TP59.1 U3.2 | length 2970.3
  Top Layer w10: C15.2@730,1423.34 730,1483.35 R40.1@733.5,1486.85 v1(733.5,1530.35) 798.15,1595 1445,1595 1576.38,1726.38 1576.38,2026.38 1680,2130 1880,2130 1910,2160 J22.3@1910,2265 ; U3.2@867.4,1410.83 U3.2@870.91,1414.33 ; v1(1090.76,1144.4) R62.2@1138.18,1144.4
  Top Layer w20: TP59.1@515,1385 596.5,1466.5 R41.2@596.5,1502.17 646.17,1502.17 C16.2@665,1483.34 668.5,1486.85 R40.1@733.5,1486.85 C15.2@733.5,1426.85 ; C15.2@730,1423.34 786.65,1423.34 795.67,1414.33 U3.2@870.91,1414.33
  Bottom Layer w10: v1@733.5,1538.5 v1(733.5,1530.35) 917.85,1346 999,1346 1060,1285 1060,1175.17 v1(1090.76,1144.4)
CT2_IN_+: J21.3 J26.2 R89.2 | length 2117.3
  Top Layer w20: R89.2@2202.94,1087.4 2245,1087.4 2260,1072.4 2260,1045 2270,1035 J26.2@2320,1035
  Bottom Layer w20: J26.2@2320,1035 2460,1035 2655,1230 2655,1885 2600,1940 2600,2215 2756.85,2371.85 J21.3@3074,2371.85
CT2_IN_-: C78.2 C79.2 J23.3 R94.1 R95.2 R105.2 TP60.1 U13.2 | length 2428.5
  Top Layer w10: R105.2@1871.08,937.67 1900.85,937.67 1911,947.82 1911,1200.4 v1(1935,1224.4) R94.1@1985,1224.4
  Top Layer w20: U13.2@2060,1364.17 2060,1292.97 2048.51,1281.47 2048.51,1220.9 1988.51,1220.9 C79.2@1988.51,1155.9 1962.94,1130.33 R95.2@1962.94,1087.4 2002.6,1087.4 TP60.1@2085,1005
  Bottom Layer w10: v1(1935,1224.4) 1939.4,1224.4 2440,1725 2440,2340 2471.85,2371.85 J23.3@2639,2371.85
CT3_IN_+: J27.2 J37.3 R106.2 | length 2037.4
  Top Layer w20: R106.2@5305,1256.5 5363.5,1256.5 5375,1245 5375,1185 5395,1165 J27.2@5440,1165
  Bottom Layer w10: J37.3@4880,2581.85 4953.15,2581.85 4970,2565 4970,2140 4994.53,2115.47 4994.53,1375.47 5030,1340 5265,1340 J27.2@5440,1165
CT3_IN_-: C48.2 C52.2 J41.3 R111.1 R112.2 R114.2 TP61.1 U6.2 | length 2475.2
  Top Layer w10: J41.3@4480,2371.85 4605.15,2371.85 4652,2325 4875,2325 4965,2235 4965,1463.82 v1(5035.32,1393.5) R111.1@5080.32,1393.5 ; v1(5451.59,1523.34) R114.2@5496.59,1523.34
  Top Layer w20: U6.2@5150.31,1535.12 5150.31,1453.46 5143.82,1446.97 C48.2@5143.82,1395 5142.33,1393.5 R111.1@5080.32,1393.5 5083.82,1390 C52.2@5083.82,1325 5065,1306.18 R112.2@5065,1256.5 5113.5,1256.5 TP61.1@5185,1185
  Bottom Layer w10: v1(5035.32,1393.5) 5321.75,1393.5 v1(5451.59,1523.34)
CT4_IN_+: J29.2 J38.3 R122.2 | length 2005.3
  Top Layer w20: J29.2@6873.5,1562.8 6877.01,1559.29 R122.2@6877.01,1441.5
  Bottom Layer w10: J38.3@5555,2670.01 5555,2490 6365,1680 6756.3,1680 J29.2@6873.5,1562.8
CT4_IN_-: C95.2 C96.2 J42.3 R127.1 R128.2 R130.2 TP62.1 U15.2 | length 3306.4
  Top Layer w10: R130.2@6193.7,1253.5 6193.7,1196.3 6220,1170 v1(6740,1170) R127.1@6740,1216.81
  Top Layer w20: U15.2@6597.28,1342.8 6622.2,1342.8 6688.19,1276.81 6740,1276.81 R127.1@6740,1216.81 6743.5,1220.32 C96.2@6808.51,1220.32 6827.33,1201.5 R128.2@6877.01,1201.5 6877.01,1242.01 6900,1265 6930,1265 TP62.1@6985,1320
  Bottom Layer w10: J42.3@5560,2250 5560,2190 5580,2170 5750,2170 5885,2035 5885,1680.81 5930.81,1635 6600,1635 6773.5,1461.5 6773.5,1203.5 v1(6740,1170)
CT_1_OUT: C20.1 J6.3 R45.2 | length 750.3
  Top Layer w10: R45.2@1755,2054.76 C20.1@1822.09,2054.76 1919.76,2054.76 1955,2090 1955,2310 1980,2335 2165,2335 2190,2360 J6.3@2250,2360
CT_2_OUT: C84.1 J7.3 R99.2 | length 999.4
  Top Layer w10: R99.2@2220,2021.5 C84.1@2285,2021.5 2285,2210 2595,2520 2690,2520 2710,2540 2710,2580 2764,2634 J7.3@2764,2701.85
CT_3_OUT: C90.1 J39.3 R118.2 | length 1834.3
  Top Layer w10: v1(5330,1885) 5386.5,1885 C90.1@5390,1888.5 R118.2@5460,1888.5
  Bottom Layer w10: J39.3@4580,2701.85 4580,2795 4610,2825 4805,2825 4970,2660 5077,2660 5160,2577 5160,2290 5300,2150 5390,2150 5410,2130 5410,1908.5 5386.5,1885 v1(5330,1885)
CT_4_OUT: C100.1 J40.3 R134.2 | length 739.6
  Top Layer w10: v1(5675,2135) C100.1@5733.5,2135 R134.2@5733.5,2065
  Bottom Layer w10: J40.3@5235,2350.01 5299.99,2350.01 5315,2335 5315,2195 5330,2180 5515,2180 5560,2135 v1(5675,2135)
GND: C9.1 C10.1 C11.1 C120.1 D19.2 D20.2 R28.1 R34.1 R172.2 U2.4 | length 591.1
  Top Layer w20: v1(1241.26,3805.6) R34.1@1306.12,3805.6 ; v1(1242.39,3966.85) C10.1@1290.57,3966.85 ; v1(1260,4015) 1210,4015 R172.2@1210,4035 1210,4050 1215,4055 v1(1260,4055) ; v1(1411.69,3921.69) D19.2@1411.69,3965 ; v1(1437.71,3869.14) U2.4@1481.12,3869.14 ; v1(1476.5,3445) C11.1@1476.5,3486.85 ; v1(1777.62,3555.33) C9.1@1777.62,3603.51 ; R28.1@1806.12,3691.42 v1(1873.58,3691.42) ; C120.1@2015,4041.5 v1(2058.5,4041.5)
  Bottom Layer w20: D20.2@1396.69,3555 v1(1396.69,3608.31)
GND1: C25.2 C26.2 C27.2 C28.2 C29.2 C30.2 C31.1 C33.1 C35.2 C36.2 C37.2 C38.2 C39.2 C40.2 C41.2 C42.2 D5.2 D6.1 J10.2 J11.2 J12.2 L4.2 R61.2 R70.2 U5.2 U5.3 U5.19 U5.25 | length 529.2
  Top Layer w8: v1(6451.26,473.74) U5.19@6451.26,510 ; U5.25@6530,555.28 U5.2@6575.28,555.28
  Top Layer w9: U5.25@6510.31,574.96 U5.3@6575.28,574.96
  Top Layer w20: v1(4280,185) 4280,230 4285,235 R70.2@4300,235 4320,235 v1(4320,185) ; v1(6081.5,481.5) C33.1@6128.5,481.5 ; C33.1@6132.01,485 C31.1@6197.01,485 ; C37.2@6740,498.98 v1(6783.98,498.98)
  Bottom Layer w20: v1(6304.02,370.67) C42.2@6348.82,370.67 ; v1(6397.72,308.98) R61.2@6442.52,308.98
  other v1: 6503,62 6553,62 5770,75 5820,75 5865,100 5910,100 5775,934 5816,934 5690,966 5731,966 5861,966 5902,966 5967,966 6008,966 6073,966 6114,966 6175,966 6216,966
  other v2: 6500.47,546.42 6462.09,584.8 6500.47,584.8 6535.85,584.5 6500.47,623.19
GND2: C109.1 C110.1 C111.1 C121.1 D21.2 D22.2 R103.2 R165.1 R171.1 U18.4 | length 593.5
  Top Layer w20: v1(5496.5,3973.5) C121.1@5545,3973.5 ; v1(5697.27,3752.27) R165.1@5765,3752.27 ; C110.1@5793.51,3840.19 v1(5793.51,3885.19) ; U18.4@6090,3574.56 6139.56,3574.56 v1(6140,3575) ; C111.1@6094.63,3956.84 v1(6094.63,4001.84) ; D21.2@6163.31,3475 v1(6163.31,3523.31) ; R171.1@6265,3638.1 v1(6330,3638.1) ; v1(6270,4010) 6320,4010 R103.2@6320,4030 6320,4045 6315,4050 v1(6270,4050) ; v1(6277.62,3431.84) C109.1@6277.62,3476.84
  Bottom Layer w20: v1(6183.31,3848.31) D22.2@6183.31,3890
"LDO FB": R87.1 R88.2 U11.7 | length 175.6
  Top Layer w10: R88.2@3936.3,1698.5 R87.1@4006.3,1698.5 4009.25,1695.55 U11.7@4009.25,1594.17
NetC1_1: C1.1 R1.2 R6.1 U1.2 | length 280.2
  Top Layer w10: U1.2@1525,3129.14 1525,3171.85 1535,3181.85 ; R6.1@1529.25,3229.73 1525,3225.48 1525,3191.85 1535,3181.85 ; R1.2@1596.1,3296.23 C1.1@1596.1,3231.23 1596.1,3191.95 1586,3181.85 1535,3181.85
NetC1_2: C1.2 R1.1 R8.1 R204.2 TP3.1 U1.1 | length 438.9
  Top Layer w10: U1.1@1575,3129.14 1662.83,3129.14 1662.83,3227.49 C1.2@1659.09,3231.23 ; R1.1@1659.09,3296.23 C1.2@1659.09,3231.23 ; R8.1@1663.7,3130 R204.2@1765,3130 ; TP3.1@1740,3231.85 1739.37,3231.23 C1.2@1659.09,3231.23
NetC2_1: C2.1 R3.2 R9.1 U1.6 | length 277.4
  Top Layer w10: R9.1@1431.12,2804.69 1431.12,2837.97 1445,2851.85 1465,2851.85 1475,2861.85 ; U1.6@1475,2914.57 1475,2861.85 ; R3.2@1499.62,2738.51 C2.1@1499.62,2804.81 1499.62,2844.23 1492,2851.85 1484.99,2851.85 1475,2861.85
NetC2_2: C2.2 R3.1 R10.1 R205.2 TP4.1 U1.7 | length 463.6
  Top Layer w10: U1.7@1525,2914.57 1525,2868.86 1562.62,2831.24 C2.2@1562.62,2804.81 ; R3.1@1562.62,2738.51 C2.2@1562.62,2804.81 ; TP4.1@1780,2880 1735,2880 1700,2845 R205.2@1700,2805 R10.1@1631.12,2805 1630.92,2804.81 C2.2@1562.62,2804.81
NetC7_2: C7.2 D1.1 JP1.1 L13.1 R11.1 R20.2 | length 690.1
  Top Layer w20: R11.1@725,3640 725,3471.85 727.09,3469.76 727.09,3594.49 ; JP1.1@730,3466.85 R20.2@838.5,3466.85 ; R20.2@840,3468.35 C7.2@910,3468.35 912.54,3470.88 D1.1@985.48,3470.88 985.48,3525.48 1010,3550 L13.1@1010,3600
NetC8_2: C8.2 D2.1 JP2.1 L14.1 R16.1 R22.2 | length 717.5
  Top Layer w20: R16.1@895,2930 895,2845 870,2820 740,2820 727.48,2807.48 JP2.1@727.48,2755.59 835.54,2755.59 R22.2@837,2757.05 904,2757.05 907.11,2760.16 D2.1@985,2760.16 985,2805 1005,2825 L14.1@1005,2890
NetC10_2: C10.2 R26.2 R27.1 | length 212.2
  Top Layer w10: R26.2@1356.5,3896.85 C10.2@1356.5,3966.85 1356.5,4031.5 1370,4045 R27.1@1428.5,4045
NetC11_2: C11.2 R32.2 R33.1 | length 134.1
  Top Layer w10: R32.2@1345,3553.35 1346.5,3551.85 R33.1@1413.5,3551.85 C11.2@1413.5,3486.85
NetC14_1: C14.1 C15.1 J19.1 R36.2 R57.2 TP5.1 U3.3 | length 1181.2
  Top Layer w10: v1(728.5,1248.17) R36.2@728.5,1291.85 ; v1(1094.5,1079.4) R57.2@1138.18,1079.4
  Top Layer w20: TP5.1@660,985 J19.1@660,1141.85 ; J19.1@665,1146.85 C14.1@665,1290.35 R36.2@727,1290.35 ; R36.2@728.5,1291.85 728.5,1358.86 C15.1@730,1360.35 795,1360.35 798.98,1364.33 U3.3@870.91,1364.33
  Bottom Layer w10: v1(728.5,1248.17) 765.33,1285 980,1285 1035,1230 1035,1138.9 v1(1094.5,1079.4)
NetC19_1: C19.1 R43.2 R44.1 U4.2 | length 286.9
  Top Layer w10: R43.2@1269.76,1214.03 C19.1@1339.76,1214.03 1379.13,1214.03 1402.81,1190.34 ; R44.1@1336.25,1145.52 1376.88,1145.52 1384.76,1153.4 1384.76,1172.29 1402.81,1190.34 ; U4.2@1450.67,1190.34 1402.81,1190.34
NetC19_2: C19.2 J5.3 R43.1 TP10.1 U4.1 | length 905.9
  Top Layer w10: TP10.1@1191.08,1292.32 1206.37,1277.02 R43.1@1269.76,1277.02 C19.2@1339.76,1277.02 1371.13,1277.02 1407.81,1240.34 U4.1@1450.67,1240.34 1490.34,1240.34 1510.67,1260.67 1510.67,1565.67 1600,1655 J5.3@1725,1655
NetC25_1: C25.1 C27.1 C28.1 C29.1 C30.1 D5.1 J15.2 R58.2 R59.2 R60.2 TP15.1 | length 328.1
  Top Layer w8: R60.2@6442.52,308.98 R60.2@6446.02,305.47
  Top Layer w20: TP15.1@5550,430 5550,380 5610,320 5650,320 5670,300 J15.2@5670,245 ; R60.2@6446.02,305.47 R59.2@6511.02,305.47
NetC31_2: C31.2 R66.1 U5.17 | length 343.8
  Top Layer w8: C31.2@6260,485 6298,485 6310,497 6310,534 6331.28,555.28 U5.17@6425.67,555.28
  Top Layer w10: R66.1@6197.01,560 6197.01,532.99 6208,522 6252.77,522 6260,514.77 C31.2@6260,485
NetC32_1: C32.1 R59.1 | length 70
  Top Layer w20: R59.1@6574.02,305.47 C32.1@6574.02,375.47
NetC32_2: C32.2 R60.1 R61.1 U5.22 | length 287
  Top Layer w8: R60.1@6446.73,376.18 6510.31,376.18 U5.22@6510.31,510
  Top Layer w20: v1(6397.72,371.97) R60.1@6442.52,371.97
  Bottom Layer w20: v1(6397.72,371.97) R61.1@6442.52,371.97
NetC33_2: C33.2 R63.2 | length 65
  Top Layer w10: C33.2@6132.01,415 R63.2@6197.01,415
NetC34_1: C34.1 R67.1 | length 74.9
  Top Layer w10: R67.1@6128.5,696.5 R67.1@6132.01,700 ; C34.1@6193.5,696.5 C34.1@6197.01,700
  Top Layer w20: R67.1@6132.01,700 C34.1@6197.01,700
NetC34_2: C34.2 R64.1 R66.2 U5.16 | length 311.9
  Top Layer w8: R66.2@6260,560 6301,560 6315.96,574.96 U5.16@6425.67,574.96
  Top Layer w20: R66.2@6260,560 C34.2@6260,700
NetC35_1: C35.1 C36.1 C39.1 C40.1 C41.1 D6.2 D7.2 J16.2 R65.2 TP16.1 U5.15 | length 264
  Top Layer w8: 6355,610 6370.35,594.65 U5.15@6425.67,594.65
  Top Layer w20: TP16.1@5550,610 5615,675 J16.2@5710,675
NetC37_1: C37.1 R68.2 U5.4 | length 245.3
  Top Layer w8: U5.4@6575.28,594.65 6630.35,594.65 6663.03,561.97 C37.1@6740,561.97 R68.2@6740,628.98
NetC42_1: C42.1 R69.2 | length 89.6
  Top Layer w20: v1(6304.02,307.68) R69.2@6348.82,307.68
  Bottom Layer w20: v1(6304.02,307.68) C42.1@6348.82,307.68
NetC47_1: C47.1 C48.1 J27.1 R107.2 R113.2 TP6.1 U6.3 | length 1043.6
  Top Layer w10: R107.2@5275.32,1393.5 R113.2@5496.43,1393.5
  Top Layer w20: U6.3@5200.31,1535.12 5200.31,1457.84 5206.81,1451.33 C48.1@5206.81,1395 5208.31,1393.5 R107.2@5275.32,1393.5 5276.81,1392.01 C47.1@5276.81,1325 5380,1325 J27.1@5440,1265 5510,1265 5530,1245 5530,1075 TP6.1@5470,1015 ; R113.2@5496.43,1393.5 R113.2@5496.59,1393.34
NetC49_1: C49.1 FB1.1 R71.2 U7.3 | length 135.9
  Top Layer w20: C49.1@3456.5,2285 R71.2@3536.5,2285 ; R71.2@3540,2281.5 FB1.1@3540,2337.44
NetC54_1: C54.1 C59.1 C60.1 D24.2 FB2.1 R74.2 R75.2 R76.2 U8.4 | length 531.8
  Top Layer w20: C59.1@3530.53,1331.5 C59.1@3527.03,1335 ; U8.4@3540,914.5 3540.5,914 v1(3685,914) ; R74.2@3607.03,1335 C59.1@3527.03,1335 ; FB2.1@3630.53,1477.44 3552.62,1477.44 C60.1@3552.62,1440 3552.62,1407.09 3527.03,1381.5 C59.1@3527.03,1335
  Bottom Layer w20: D24.2@3685,843.31 v1(3685,914)
NetC54_2: C54.2 C122.1 R75.1 R76.1 R79.2 R80.2 U8.1 U8.2 | length 678.2
  Top Layer w25: R80.2@3267.91,676.5 R79.2@3340,676.5 ; C122.1@3381.5,1064 3381.5,931.5 3340,890 R79.2@3340,676.5 ; U8.2@3540,680 U8.1@3449,680 3343.5,680 R79.2@3340,676.5
NetC61_1: C61.1 U10.5 | length 142.6
  Top Layer w20: U10.5@3875,2677.28 3875,2635 3900,2610 C61.1@3965,2610
NetC63_2: C63.2 R78.1 U9.3 | length 157.7
  Top Layer w20: R78.1@3608.15,2980.75 C63.2@3675,2980.75 3672.4,2983.35 U9.3@3672.4,3070.55
NetC64_1: C64.1 R81.2 | length 67
  Top Layer w20: R81.2@3781.5,2820 C64.1@3848.5,2820
NetC70_1: C70.1 R85.1 R86.2 U12.2 | length 252.7
  Top Layer w15: R86.2@3773.81,427.75 3774.04,427.99 R85.1@3774.04,494.26 C70.1@3839.04,494.26 3873.04,494.26 3884.04,505.26 3884.04,525.26 3891.84,533.06 U12.2@3932.4,533.06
